(* Logix 5000 project; controller Demo vendor 1 type 14 code 3 rev 13.27; software revision 13.00 *)

TASK MainTask (continuous, watchdog 500 ms) : MainProgram

MODULES
   Local : vendor 1 type 14 code 3 (ICP 1, rev 13.27)
      Input_card_1 : 1756-IA16 (ICP 2, rev 2.1, Input RPI 10 ms)
       : 1756-OW16I (ICP 3, rev 1.1)
      Enet_Card : 1756-ENBT (ICP 0, Ethernet 192.168.1.55, rev 1.1)
END_MODULES

PROGRAM MainProgram   (* routine attr 65 MainRoutine *)

ROUTINE MainRoutine   (* ladder *)
END_ROUTINE
END_PROGRAM
